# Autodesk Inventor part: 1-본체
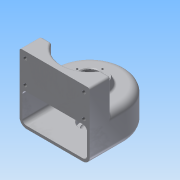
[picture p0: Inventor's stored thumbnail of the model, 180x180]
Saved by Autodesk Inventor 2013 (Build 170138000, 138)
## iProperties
Created: 2015-02
Part Number: 1-본체
Material: 알루미늄 6061
Document SubType Name: Modeling
Designer: MYHOME
Density: 2.71 g/cm^3
Mass: 575.526 g
Surface Area: 706.56 cm^2
Volume: 212.371 cm^3
Author: MYHOME
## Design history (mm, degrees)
sketch "스케치1"
  geometry: L1 (50, 0)-(50, -50); L2 (-50, 0)-(-50, -50); L3 (-50, -50)-(50, -50); A1 r 50 centre (0, 0) between (50, 0) and (-50, 0); 1 further point
  constraints: 6 end point, 2 point on circle, 2 tangent, 1 centre point, 1 coincident, 1 horizontal, 1 parallel, 1 vertical
  dimensions: "d0" = 50 radius of A1; "d2" = 50 distance of L1.start L1.end
extrude "돌출1" new body sketch "스케치1" distance "d3" = 50; taper "d4" = 0 deg
feature "쉘1" dims "d10" = 4
sketch "스케치2"
  geometry: L1 (-50, 0)-(-50, -50) reference; L2 (-50, -50)-(50, -50) reference; L3 (50, -50)-(50, 0) reference; L4 (-50, -20)-(-34.641, -20); L5 (34.641, -20)-(50, -20); A1 r 50 centre (0, 0) between (50, 0) and (-50, 0) reference; A2 r 40 centre (0, 0) between (-34.641, -20) and (34.641, -20)
  constraints: 4 end point, 2 perpendicular, 2 point on circle, 2 point on line, 1 centre point, 1 coincident, 1 collinear
  dimensions: "d5" = 40 radius of A2; "d7" = 30 distance between parallel lines of L2 L4
extrude "돌출2" join sketch "스케치2" distance "d8" = 45; taper "d9" = 0 deg
sketch "스케치3"
  geometry: C1 r 25 at (0, 0); A1 r 40 centre (0, 0) between (-34.641, -20) and (34.641, -20) reference
  constraints: 1 centre point, 1 coincident
  dimensions: "d11" = 50 diameter of C1
extrude "돌출3" join sketch "스케치3" distance "d13" = 10; taper "d14" = -20 deg
hole "구멍1" diameter "d17" = 20; stored, may be unused: countersink angle "d21" = 90 deg, drill point angle "d23" = 0 deg; dims "d15" = 10, "d16" = 10, "d18" = 6, "d19" = 28, "d20" = 10, "d22" = 14
sketch "스케치4"
  geometry: C1 r 20 at (0, 0); A1 r 50 centre (0, 0) between (50, 0) and (-50, 0) reference
  constraints: 1 centre point, 1 coincident
  dimensions: "d24" = 40 diameter of C1
extrude "돌출4" join sketch "스케치4" distance "d26" = 9; taper "d27" = 0 deg
sketch "스케치5"
  geometry: A1 r 46 centre (0, 0) between (46, 0) and (-46, 0) reference; 1 further point
  constraints: 1 coincident
hole "구멍2" sketch "스케치5" at (0, 0) diameter "d28" = 20; stored, may be unused: countersink angle "d32" = 90 deg, drill point angle "d34" = 0 deg; dims "d29" = 6, "d30" = 28, "d31" = 8, "d33" = 10
sketch "스케치6"
  geometry: L1 (0, 95)-(100, 95) reference; L2 (8.25, 86)-(91.75, 86); L3 (91.75, 86)-(91.75, 53); L4 (91.75, 53)-(8.25, 53); L5 (8.25, 53)-(8.25, 86); L6 (8.25, 86)-(91.75, 53); L7 (91.75, 86)-(8.25, 53); 8 further points
  constraints: 12 end point, 4 coincident, 4 midpoint, 2 parallel, 1 horizontal, 1 perpendicular, 1 vertical alignment
  dimensions: "d35" = 83.5 distance of L2.start L2.end; "d37" = 33 distance of L4.end L2.start; "d38" = 9 distance between parallel lines of L2 L1
hole "구멍3" sketch "스케치6" at (8.25, 86), (91.75, 86), (91.75, 53), (8.25, 53) diameter "d39" = 5.134; stored, may be unused: countersink angle "d43" = 90 deg, drill point angle "d45" = 118 deg; dims "d40" = 10, "d41" = 28, "d42" = 8, "d44" = 13
sketch "스케치7"
  geometry: C1 r 14 at (0, 0) reference; C2 r 21.36 at (0, 0) reference; A1 r 18 centre (0, 0) between (0, 18) and (18, 0); 2 further points
  constraints: 4 point on circle, 2 horizontal alignment, 2 vertical alignment, 1 centre point, 1 coincident
  dimensions: "d46" = 36 diameter of A1
hole "구멍4" sketch "스케치7" at (0, 18), (18, 0), (-18, 0), (0, -18) diameter "d48" = 2.459; stored, may be unused: countersink angle "d52" = 90 deg, drill point angle "d54" = 118 deg; dims "d49" = 6, "d50" = 28, "d51" = 8, "d53" = 9
node "작업 평면1"
sketch "스케치8"
  geometry: L1 (0, 0)-(-100, 0) reference; 3 further points
  constraints: 1 midpoint, 1 vertical alignment, 1 other
  dimensions: "d56" = 25 distance from line of L1 point (-50, 25)
feature "엠보싱1" sketch "스케치8" dims "d0" = 50, "d2" = 50, "d57" = 0.5, "d58" = 0
fillet "모깎기1" dims "d59" = 10, "d60" = 6, "d61" = 0.3
fillet "모깎기2" dims "d62" = 3
fillet "모깎기3" dims "d63" = 3
fillet "모깎기4" dims "d64" = 3
chamfer "모따기1" distance "d65" = 1; stored, may be unused: second distance "d66" = 2, angle "d67" = 45 deg
node "솔리드1"
